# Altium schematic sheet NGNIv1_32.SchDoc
size A4
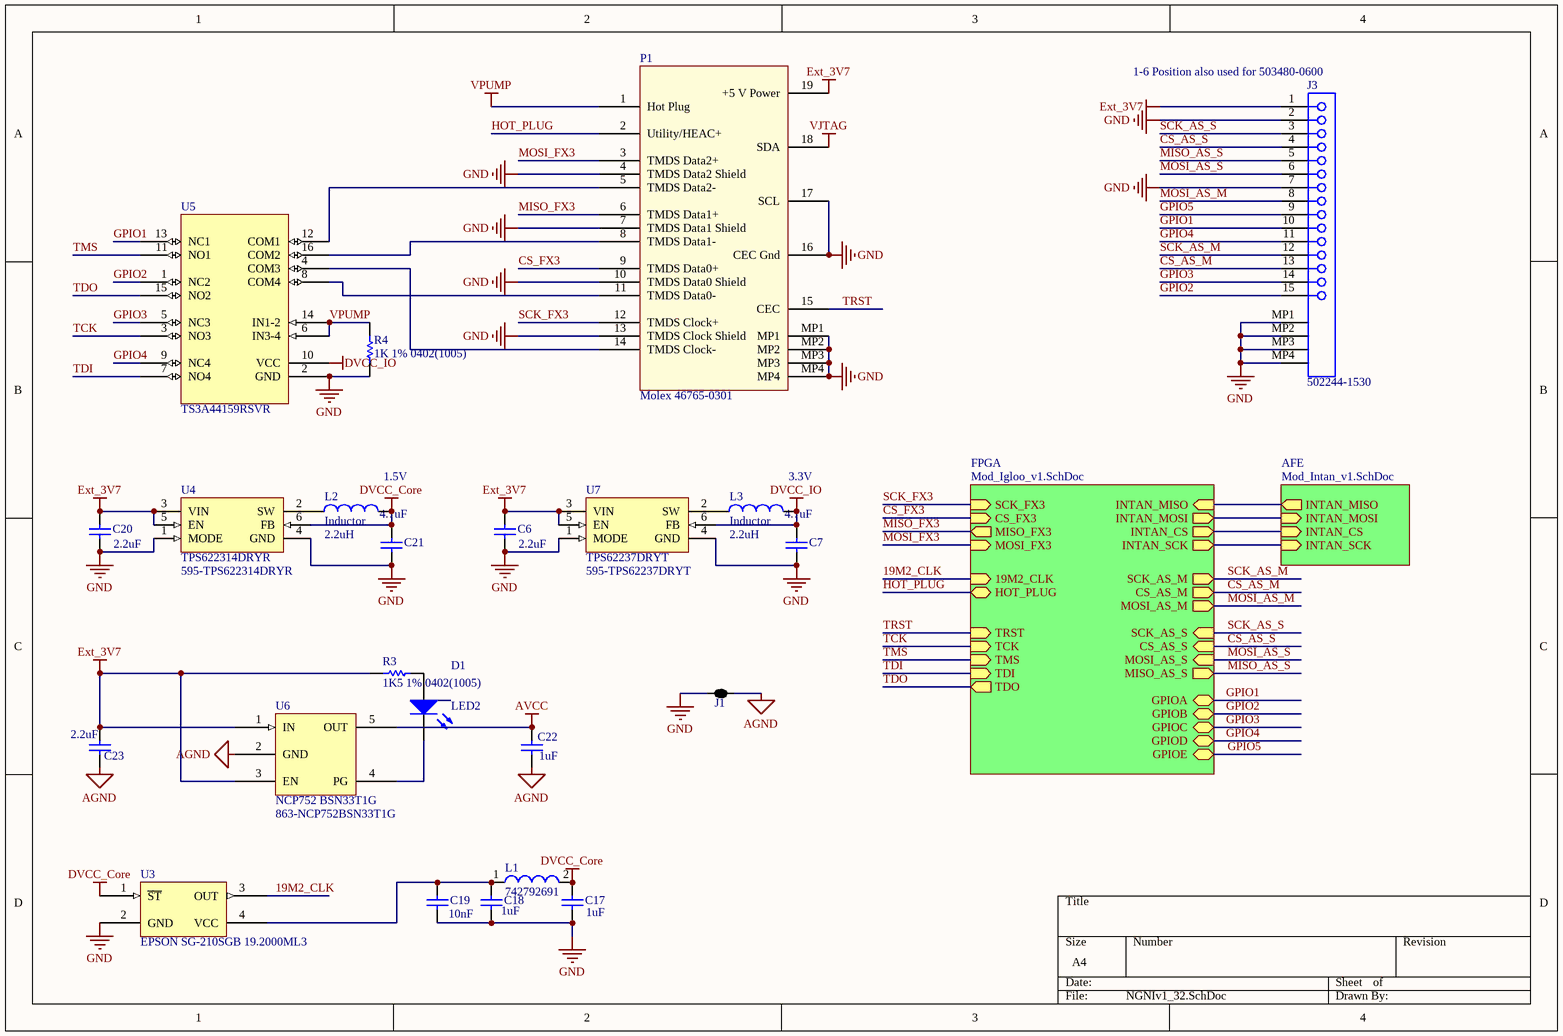
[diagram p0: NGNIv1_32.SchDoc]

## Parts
C6  value 2.2uF  [CAPC0402(1005)60_L]  (hidden comment: CAP 2.2uF 10V 0402(1005))
C7  value 4.7uF  [CAPC0402(1005)60_N]  (hidden comment: CAP 4.7uF 6.3V 0402(1005))
C17  value 1uF  [CAPC0402(1005)60_L]  (hidden comment: CAP 1uF 16V 0402(1005))
C18  value 1uF  [CAPC0402(1005)60_L]  (hidden comment: CAP 1uF 16V 0402(1005))
C19  value 10nF  [CAPC0402(1005)60_L]  (hidden comment: CAP 10nF 25V 0402(1005))
C20  value 2.2uF  [CAPC0402(1005)60_L]  (hidden comment: CAP 2.2uF 10V 0402(1005))
C21  value 4.7uF  [CAPC0402(1005)60_N]  (hidden comment: CAP 4.7uF 6.3V 0402(1005))
C22  value 1uF  [CAPC0402(1005)60_L]  (hidden comment: CAP 1uF 16V 0402(1005))
C23  value 2.2uF  [CAPC0603(1608)100_L]  (hidden comment: CAP 2.2uF 25V 0603(1608))
D1  LED2  [LED 0610]
J1  2 way net tie junction  [2way_micro]  (value not drawn)  (net tie, no BOM)
J3  502244-1530  [MOLX-502244-1530]
L1  742792691  [SMD-0603]
L2  Inductor  value 2.2uH  [2029]
L3  Inductor  value 2.2uH  [2029]
P1  Molex 46765-0301  [MOLEX 0467650301]
R3  1K5 1% 0402(1005)  [RESC0402(1005)_L]
R4  1K 1% 0402(1005)  [RESC0402(1005)_L]
U3  EPSON SG-210SGB 19.2000ML3  [SG-210S*B]
U4  TPS622314DRYR  Supplier Part Number 1: 595-TPS622314DRYR  [DRY0006A]
U5  TS3A44159RSVR  [UQFN-4]
U6  NCP752 BSN33T1G  Supplier Part Number 1: 863-NCP752BSN33T1G  [TSOP5 NCP752]
U7  TPS62237DRYT  Supplier Part Number 1: 595-TPS62237DRYT  [DRY0006A]

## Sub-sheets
AFE = Mod_Intan_v1.SchDoc: INTAN_MISO (out), INTAN_MOSI (in), INTAN_CS (in), INTAN_SCK (in)
FPGA = Mod_Igloo_v1.SchDoc: CS_AS_M (out), SCK_AS_S (in), HOT_PLUG, SCK_AS_M (out), CS_AS_S (in), SCK_FX3 (in), MISO_FX3 (out), MOSI_AS_S (in), INTAN_MOSI (out), 19M2_CLK (in), MOSI_AS_M (out), MISO_AS_S (out), INTAN_MISO (in), TRST (in), MOSI_FX3 (in), TDO (out), TMS (in), CS_FX3 (in), TCK (in), INTAN_CS (out), INTAN_SCK (out), TDI (in), GPIOA, GPIOC, GPIOE, GPIOB, GPIOD

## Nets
AGND: C22.1 C23.1 J1.2 U6.2(GND)
AVCC: C22.2 U6.5(OUT)
DVCC_Core: C17.2 C21.1 L1.2 L2.2 U3.1(~{ST}) U4.6(FB)
DVCC_IO: C7.1 L3.2 U5.10(VCC) U7.6(FB)
Ext_3V7: C6.2 C20.2 C23.2 J3.1 P1.19(+5_V_Power) R3.1 U4.3(VIN) U4.5(EN) U6.1(IN) U6.3(EN) U7.3(VIN) U7.5(EN)
GND: C6.1 C7.2 C17.1 C18.1 C19.1 C20.1 C21.2 J1.1 J3.2 J3.7 J3.MP1 J3.MP2 J3.MP3 J3.MP4 P1.4(TMDS_Data2_Shield) P1.7(TMDS_Data1_Shield) P1.10(TMDS_Data0_Shield) P1.13(TMDS_Clock_Shield) P1.16(CEC_Gnd) P1.17(SCL) P1.MP1 P1.MP2 P1.MP3 P1.MP4 R4.2 U3.2(GND) U4.1(MODE) U4.4(GND) U5.2(GND) U7.1(MODE) U7.4(GND)
VJTAG: P1.18(SDA)
VPUMP: P1.1(Hot_Plug) R4.1 U5.6(IN3-4) U5.14(IN1-2)
19M2_CLK: U3.3(OUT) ; sheet FPGA/19M2_CLK
CS_AS_M: J3.13 ; sheet FPGA/CS_AS_M
CS_AS_S: J3.4 ; sheet FPGA/CS_AS_S
CS_FX3: P1.9(TMDS_Data0+) ; sheet FPGA/CS_FX3
GPIO1: J3.10 U5.13(NC1) ; sheet FPGA/GPIOA
GPIO2: J3.15 U5.1(NC2) ; sheet FPGA/GPIOB
GPIO3: J3.14 U5.5(NC3) ; sheet FPGA/GPIOC
GPIO4: J3.11 U5.9(NC4) ; sheet FPGA/GPIOD
GPIO5: J3.9 ; sheet FPGA/GPIOE
HOT_PLUG: P1.2(Utility/HEAC+) ; sheet FPGA/HOT_PLUG
MISO_AS_S: J3.5 ; sheet FPGA/MISO_AS_S
MISO_FX3: P1.6(TMDS_Data1+) ; sheet FPGA/MISO_FX3
MOSI_AS_M: J3.8 ; sheet FPGA/MOSI_AS_M
MOSI_AS_S: J3.6 ; sheet FPGA/MOSI_AS_S
MOSI_FX3: P1.3(TMDS_Data2+) ; sheet FPGA/MOSI_FX3
SCK_AS_M: J3.12 ; sheet FPGA/SCK_AS_M
SCK_AS_S: J3.3 ; sheet FPGA/SCK_AS_S
SCK_FX3: P1.12(TMDS_Clock+) ; sheet FPGA/SCK_FX3
TCK: U5.3(NO3) ; sheet FPGA/TCK
TDI: U5.7(NO4) ; sheet FPGA/TDI
TDO: U5.15(NO2) ; sheet FPGA/TDO
TMS: U5.11(NO1) ; sheet FPGA/TMS
TRST: P1.15(CEC) ; sheet FPGA/TRST
NetC18_2: C18.2 C19.2 L1.1 U3.4(VCC)
NetD1_1: D1.1(A) R3.2
NetD1_2: D1.2(K) U6.4(PG)
NetL2_1: L2.1 U4.2(SW)
NetL3_1: L3.1 U7.2(SW)
NetP1_5: P1.5(TMDS_Data2-) U5.12(COM1)
NetP1_8: P1.8(TMDS_Data1-) U5.16(COM2)
NetP1_11: P1.11(TMDS_Data0-) U5.8(COM4)
NetP1_14: P1.14(TMDS_Clock-) U5.4(COM3)
(unnamed): sheet FPGA/INTAN_MOSI, sheet AFE/INTAN_MOSI
(unnamed): sheet FPGA/INTAN_MISO, sheet AFE/INTAN_MISO  [a separate net that carries the same name]
(unnamed): sheet FPGA/INTAN_CS, sheet AFE/INTAN_CS  [a separate net that carries the same name]
(unnamed): sheet FPGA/INTAN_SCK, sheet AFE/INTAN_SCK  [a separate net that carries the same name]

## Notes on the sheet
- (near J3) 1-6 Position also used for 503480-0600
- (near L2) 1.5V
- (near L3) 3.3V

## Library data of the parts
C6 C20 = CMP-1034-02128-1: CAP 2.2uF 10V Â±20% 0402 (1005 Metric) Thickness 0.6mm SMD; Case-Metric: 1005; Case-EIA: 0402
C7 C21 = CMP-1034-02137-1: CAP 4.7uF 6.3V Â±20% 0402 (1005 Metric) Thickness 0.6mm SMD; Case-Metric: 1005; Case-EIA: 0402
C17 = CMP-1034-02119-1: CAP 1uF 16V Â±10% 0402 (1005 Metric) Thickness 0.6mm SMD; Case-EIA: 0402; Case-Metric: 1005
C18 = CMP-1034-02120-1: CAP 1uF 16V Â±20% 0402 (1005 Metric) Thickness 0.6mm SMD; Case-EIA: 0402; Case-Metric: 1005
C19 = CMP-1034-01879-1: CAP 10nF 25V ±5% 0402 (1005 Metric) Thickness 0.6mm SMD; Case-Metric: 1005; Case-EIA: 0402
C22 = CMP-1034-02119-1: CAP 1uF 16V ±10% 0402 (1005 Metric) Thickness 0.6mm SMD; Case-Metric: 1005
C23 = CMP-1035-02767-1: CAP 2.2uF 25V ±10% 0603 (1608 Metric) Thickness 1mm SMD; Case-Metric: 1608
D1 = LED2: Typical RED, GREEN, YELLOW, AMBER GaAs LED
J1 = 2way
J3 = MOLX-502244-1530
L1 = CMP-0220-00115-1: SMD EMI Suppression Ferrite Bead WE-CBF, Z = 1500 Ohm
L2 L3 = Inductor: LQM21PN2R2; Code_IEC: 1005
P1 = Molex 46765-0301: Micro HDMI
R3 = CMP-1011-00528-1: 1K5 0.063W 1% 0402 (1005 Metric)  SMD; Case-Metric: 1005; Value: 1500.00 Ohm; Case-EIA: 0402
R4 = CMP-1011-00510-1: 1K 0.063W 1% 0402 (1005 Metric)  SMD; Value: 1000.00 Ohm; Case-Metric: 1005; Case-EIA: 0402
U4 = TPS622314DRYR: Voltage Regulators - Switching Regulators 3MHz,500mA Step- Down Converter; Manufacturer: Texas Instruments; CompType: IC; PIN_COUNT: 6; Input Voltage: 2.05 V to 6 V; Input Voltage MAX: 6 V; Number of Outputs: 1 Output; Output Voltage: 1.5 V; Topology: Buck; Input Voltage MIN: 2.05 V
U5 = TS3A44159RSVR: 0.45-Ω Quad SPDT Analog Switch 4-Channel 2:1 Multiplexer – Demultiplexer  With Two Controls
U6 = NCP752 BSN33T1G: 3.3V LDO 200ma ultra low quiescent current, ultra low noise
U7 = TPS62237DRYT: Voltage Regulators - Switching Regulators 3MHz,500mA Step- Down Converter; PartNumber: TPS622314DRY; Manufacturer: Texas Instruments; Manufacturer Part Number: TPS622314DRYR; CompType: IC; PIN_COUNT: 6; Input Voltage: 2.05 V to 6 V; Input Voltage MAX: 6 V; Number of Outputs: 1 Output; Output Voltage: 1.5 V; Topology: Buck; Input Voltage MIN: 2.05 V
